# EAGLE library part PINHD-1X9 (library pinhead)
PIN HEADER
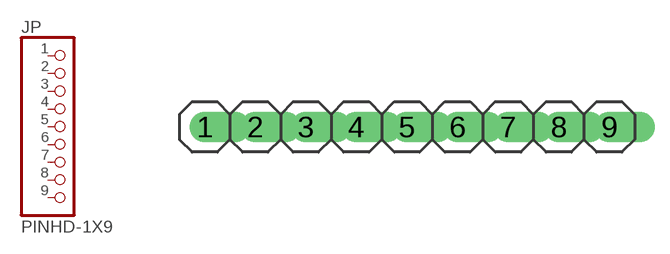
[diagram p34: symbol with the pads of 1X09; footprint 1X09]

Designator prefix JP

## PINHD-1X9  [1X09]
1  1  pas
2  2  pas
3  3  pas
4  4  pas
5  5  pas
6  6  pas
7  7  pas
8  8  pas
9  9  pas

## Footprint 1X09 (pad centres in mm)
PIN HEADER
drill 1.016 offset: 1 -10.16,0; 2 -7.62,0; 3 -5.08,0; 4 -2.54,0; 5 0,0; 6 2.54,0; 7 5.08,0; 8 7.62,0; 9 10.16,0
